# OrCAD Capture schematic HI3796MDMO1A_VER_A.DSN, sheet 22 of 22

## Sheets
22 SHEET_22: size B
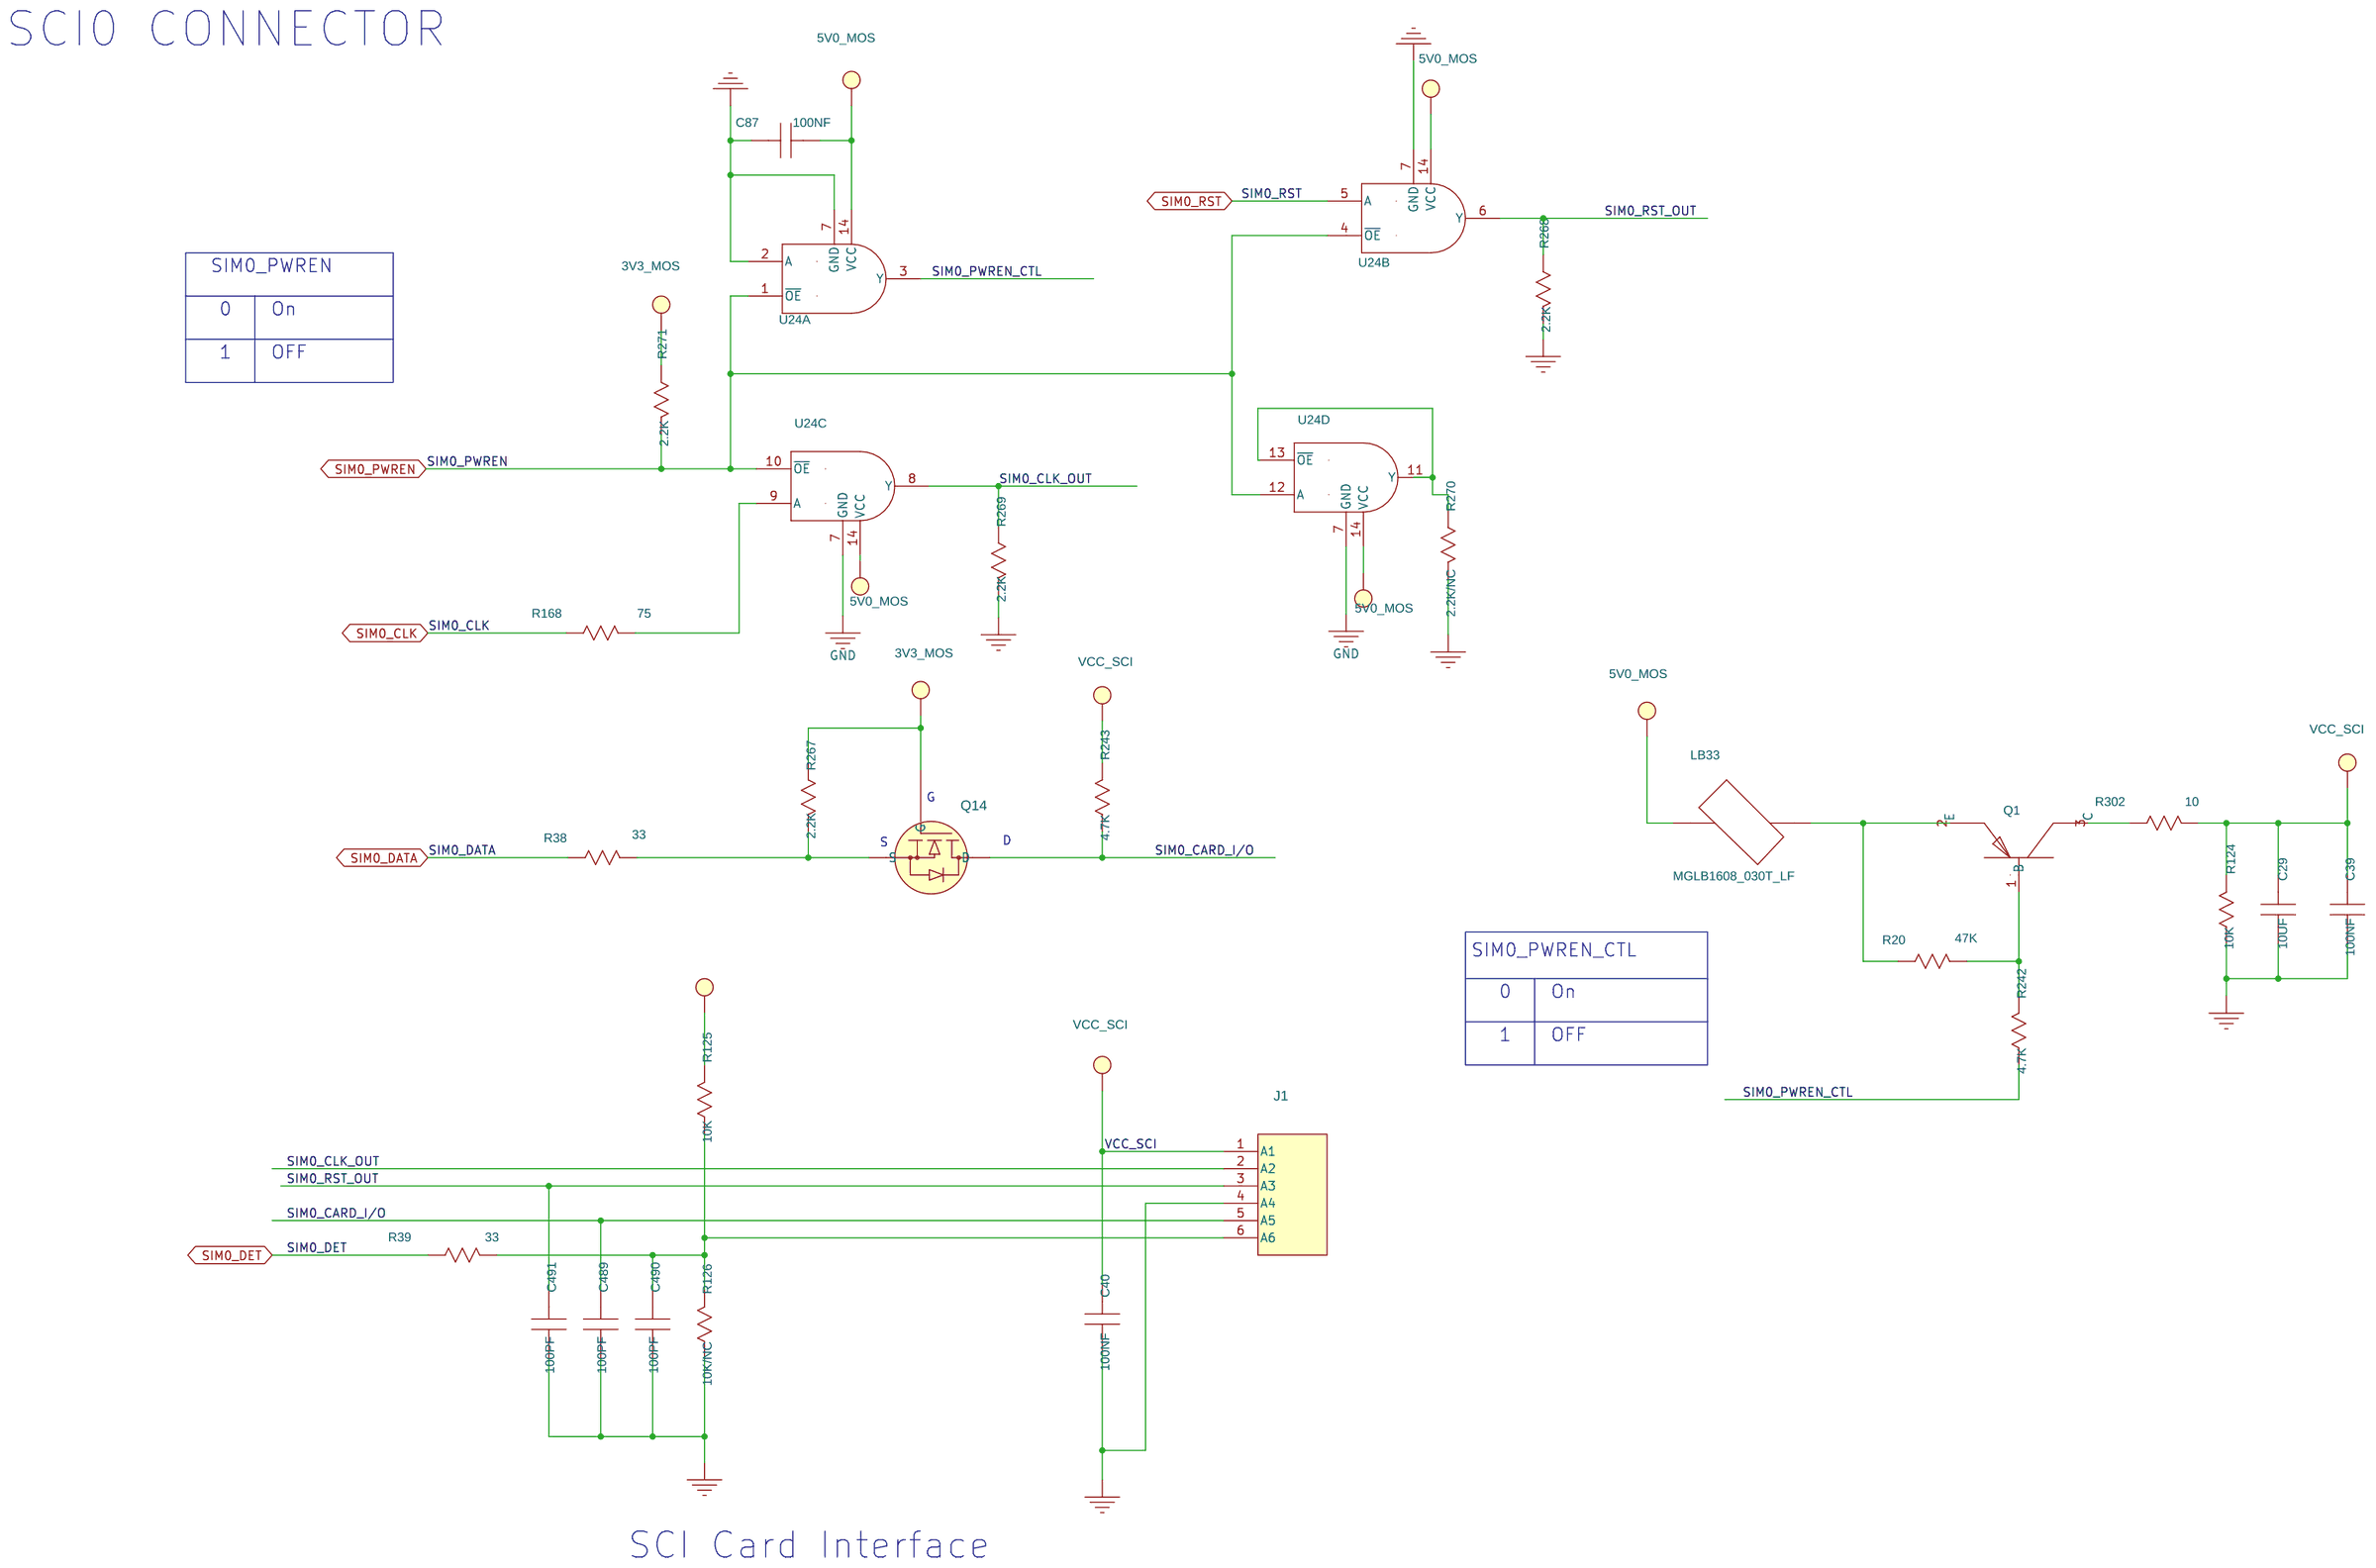
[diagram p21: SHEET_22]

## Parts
C29  10UF  [SC0805]
C39  100NF  [SC0402]
C40  100NF  [SC0402]
C87  100NF  [SC0402]
C489  100PF  [SC0402]
C490  100PF  [SC0402]
C491  100PF  [SC0402]
J1  SIP6  [SIP-6P-100]
LB33  LB  [SL0603]
Q1  PNP-BEC  [SOT23]
Q14  FETN-GSD  [SOT23]
R20  47K  [SR0402]
R38  33  [SR0402]
R39  33  [SR0402]
R124  10K  [SR0402]
R125  10K  [SR0402]
R126  10K/NC  [SR0402]
R168  75  [SR0402]
R242  4.7K  [SR0402]
R243  4.7K  [SR0402]
R267  2.2K  [SR0402]
R268  2.2K  [SR0402]
R269  2.2K  [SR0402]
R270  2.2K/NC  [SR0402]
R271  2.2K  [SR0402]
R302  10  [SR0402]
U24  74F125PC  [SOP14-50-150]  (sections A,B,C,D)

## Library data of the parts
C29 = C_0: %182%%238%%182%%168%%185%%164%%215%%247%%181%%231%%209%%185%(V): 25; %195%%232%%202%%246%: SMD陶瓷电容-25V-10000NF-+/-20%-X5R-0805; %208%%161%%192%%224%%195%%251%%179%%198%: SMD陶瓷电容; CODE: 8071629; COMPONENT_HIGH_MAX: 1.45MM; DEVICE: C2012X5R1E106KT000N1
C39 C40 C87 = C_0: %182%%238%%182%%168%%185%%164%%215%%247%%181%%231%%209%%185%(V): 16; %195%%232%%202%%246%: SMD陶瓷电容-16V-100NF-±10%-X7R-0402; %208%%161%%192%%224%%195%%251%%179%%198%: SMD陶瓷电容; CODE: 8070614; COMPONENT_HIGH_MAX: 0.6MM; DEVICE: RMEMK105BJ104KV_FR
C489-C491 = C_0: %182%%238%%182%%168%%185%%164%%215%%247%%181%%231%%209%%185%(V): 50; %195%%232%%202%%246%: SMD陶瓷电容-50V-0.1NF-±5%-NPO-0402; %208%%161%%192%%224%%195%%251%%179%%198%: SMD陶瓷电容; CODE: 8070450; COMPONENT_HIGH_MAX: 0.55MM; DEVICE: 04025A101JAT2A
J1 = SIP6: %195%%232%%202%%246%: 普通插座-6PIN-单排-直式-2.5MM-2MM-THT-3A; %208%%161%%192%%224%%195%%251%%179%%198%: 普通插座; CODE: 14100078; COMPONENT_HIGH_MAX: 7.25MM; DEVICE: TJC3_6A_34HW
LB33 = LB_v2: %195%%232%%202%%246%: EMI磁珠-30OHM-0.05OHM-0.4A-0603; %208%%161%%192%%224%%195%%251%%179%%198%: EMI磁珠; CODE: 10070003; COMPONENT_HIGH_MAX: 0.95MM; DEVICE: MGLB1608_030T_LF
Q1 = PNP-BEC_5: %195%%232%%202%%246%: 三极管-PNP-65V-100MA-350MW-650MV@100MA-SOT-23-220@2MA; %208%%161%%192%%224%%195%%251%%179%%198%: 三极管; CODE: 15050078; DEVICE: BC856B215
Q14 = FETN-GSD_2: %195%%232%%202%%246%: MOSFET-N CHANNEL-60V-0.115A-7.5OHM-20V-SOT-23; %208%%161%%192%%224%%195%%251%%179%%198%: MOSFET; COMPONENT_HIGH_MAX: 1.1MM; DEVICE: 2N7002LT1
R20 = R_0: %182%%238%%182%%168%%185%%166%%194%%202%(W): 0.06; %195%%232%%202%%246%: 片式厚膜电阻器-0.0625W-47000OHM-+/-1%-0402; %208%%161%%192%%224%%195%%251%%179%%198%: 片式厚膜电阻器; %215%%232%%214%%181%%212%%202%%208%%237%%198%%171%%178%%238%: +/-1%; CODE: 7090829; COMPONENT_HIGH_MAX: 0.4MM; DEVICE: RK73H1ELTP4702F
R38 R39 = R_0: %182%%238%%182%%168%%185%%166%%194%%202%(W): 0.06; %195%%232%%202%%246%: 片式厚膜电阻器-0.0625W-33OHM-±5%-0402; %208%%161%%192%%224%%195%%251%%179%%198%: 片式厚膜电阻器; %215%%232%%214%%181%%212%%202%%208%%237%%198%%171%%178%%238%: ±5%; CODE: 7090861; COMPONENT_HIGH_MAX: 0.4MM; DEVICE: RK73B1ETTP330J
R124-R126 = R_0: %182%%238%%182%%168%%185%%166%%194%%202%(W): 0.06; %195%%232%%202%%246%: 片式厚膜电阻器-0.0625W-10000OHM-±5%-0402; %208%%161%%192%%224%%195%%251%%179%%198%: 片式厚膜电阻器; %215%%232%%214%%181%%212%%202%%208%%237%%198%%171%%178%%238%: ±5%; CODE: 7090815; COMPONENT_HIGH_MAX: 0.4MM; DEVICE: RC_02W103JT
R168 = R_0: %182%%238%%182%%168%%185%%166%%194%%202%(W): 0.06; %195%%232%%202%%246%: 片式厚膜电阻器-0.0625W-75OHM-+/-1%-0402; %208%%161%%192%%224%%195%%251%%179%%198%: 片式厚膜电阻器; %215%%232%%214%%181%%212%%202%%208%%237%%198%%171%%178%%238%: +/-1%; CODE: 7091321; COMPONENT_HIGH_MAX: 0.4MM; DEVICE: RC_02W750FT
R242 R243 = R_0: %182%%238%%182%%168%%185%%166%%194%%202%(W): 0.06; %195%%232%%202%%246%: 片式厚膜电阻器-0.0625W-4700OHM-+/-5%-0402; %208%%161%%192%%224%%195%%251%%179%%198%: 片式厚膜电阻器; %215%%232%%214%%181%%212%%202%%208%%237%%198%%171%%178%%238%: +/-5%; CODE: 7090793; COMPONENT_HIGH_MAX: 0.4MM; DEVICE: RK73B1ELTP472J
R267-R271 = R_0: %182%%238%%182%%168%%185%%166%%194%%202%(W): 0.06; %195%%232%%202%%246%: 片式厚膜电阻器-0.0625W-2200OHM-+/-1%-0402; %208%%161%%192%%224%%195%%251%%179%%198%: 片式厚膜电阻器; %215%%232%%214%%181%%212%%202%%208%%237%%198%%171%%178%%238%: +/-1%; CODE: 7090810; COMPONENT_HIGH_MAX: 0.4MM; DEVICE: RC0402FR_072K2L
R302 = R_0: %182%%238%%182%%168%%185%%166%%194%%202%(W): 0.06; %195%%232%%202%%246%: 片式厚膜电阻器-0.0625W-10OHM-±5%-0402; %208%%161%%192%%224%%195%%251%%179%%198%: 片式厚膜电阻器; %215%%232%%214%%181%%212%%202%%208%%237%%198%%171%%178%%238%: ±5%; CODE: 7090730; COMPONENT_HIGH_MAX: 0.4MM; DEVICE: RC0402JR_0710R
U24 = 74F125PC: %195%%232%%202%%246%: CMOS-四三态输出驱动器-SOP14(TAPE)-25NS-6MA-CMOS-CMOS-0NS-0NS-0NS; %208%%161%%192%%224%%195%%251%%179%%198%: CMOS; CODE: 36020157; COMPONENT_HIGH_MAX: 1.75MM; DEVICE: SN74HC125DR

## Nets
3V3_MOS: Q14.1(G) R125.2(B) R267.1(A) R271.1(A) ; also on sheet 5 6 7 8 9 13 14 15 17 18 19 20 21
5V0_MOS: C87.2(B) LB33.1 U24.14(VCC) ; also on sheet 5 6 14 16 19 21
GND: C29.2(B) C39.2(B) C40.2(B) C87.1(A) C489.2(B) C490.2(B) C491.2(B) J1.4(A4) R124.1(A) R126.1(A) R268.2(B) R269.2(B) R270.2(B) U24.2(A) U24.7(GND) ; also on sheet 3 4 5 6 7 8 9 10 11 12 13 14 15 16 17 18 19 20 21
VCC_SCI: C29.1(A) C39.1(A) C40.1(A) J1.1(A1) R124.2(B) R243.1(A) R302.2(B)
SIM0_CARD_I/O: C489.1(A) J1.5(A5) Q14.3(D) R243.2(B)
SIM0_CLK: R168.1(A) ; also on sheet 6
SIM0_CLK_OUT: J1.2(A2) R269.1(A) U24.8(Y)
SIM0_DATA: R38.1(A) ; also on sheet 6
SIM0_DET: R39.1(A) ; also on sheet 6
SIM0_PWREN: R271.2(B) U24.1(~{OE}) U24.4(~{OE}) U24.10(~{OE}) U24.12(A) ; also on sheet 6
SIM0_PWREN_CTL: R242.1(A) U24.3(Y)
SIM0_RST: U24.5(A) ; also on sheet 6
SIM0_RST_OUT: C491.1(A) J1.3(A3) R268.1(A) U24.6(Y)
N486978: Q14.2(S) R38.2(B) R267.2(B)
N486990: R270.1(A) U24.11(Y) U24.13(~{OE})
N487116: R168.2(B) U24.9(A)
N487144: Q1.1(B) R20.2(B) R242.2(B)
N487156: Q1.3(C) R302.1(A)
N487184: LB33.2 Q1.2(E) R20.1(A)
N487206: C490.1(A) J1.6(A6) R39.2(B) R125.1(A) R126.2(B)

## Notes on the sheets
sheet 22
- SCI0 CONNECTOR
- SIM0_PWREN
- 0
- On
- 1
- OFF
- G
- S
- D
- SIM0_PWREN_CTL
- 0
- On
- 1
- OFF
- SCI Card Interface
